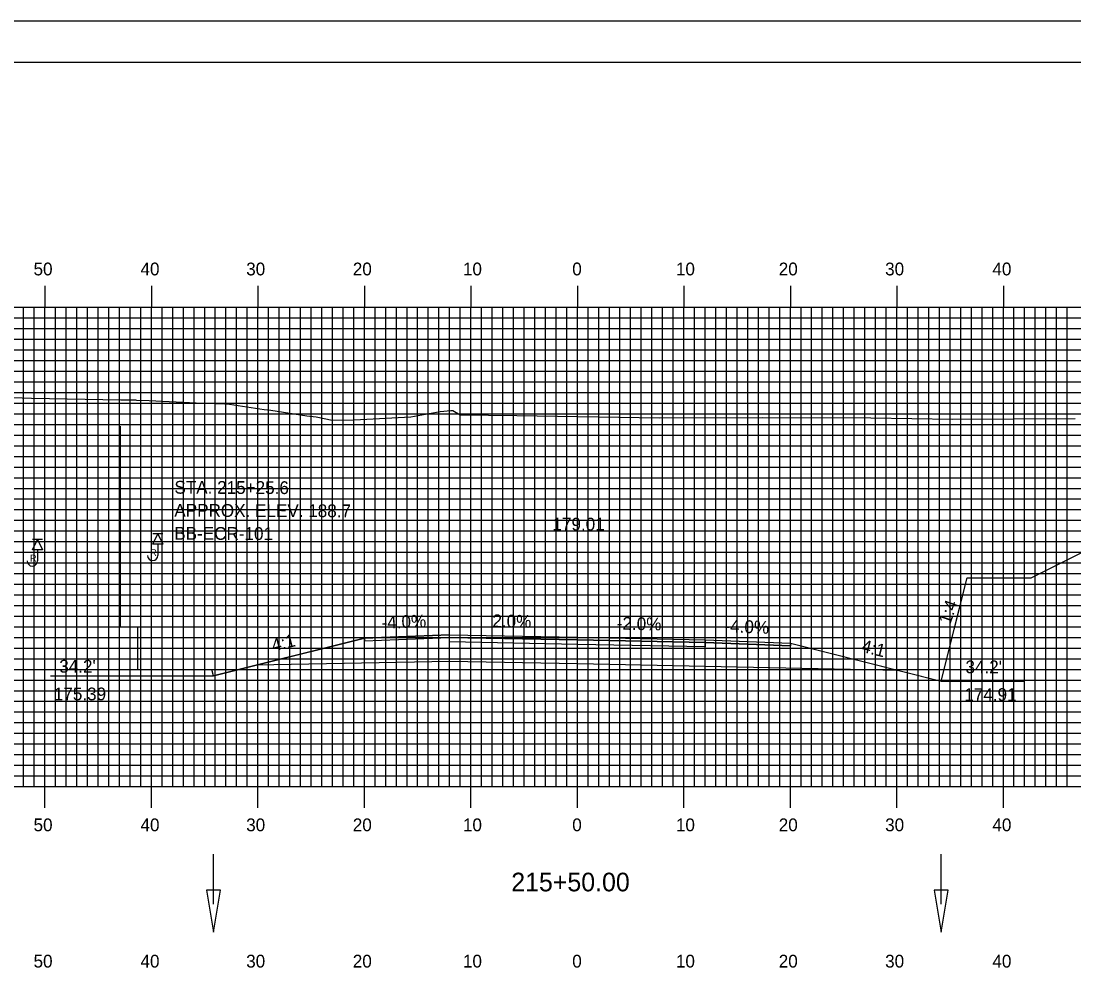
# Model space of a CAD drawing. Extents: x 1796027 to 1796370, y 442591 to 442811.
# Drawn here: x 1796140.1 to 1796239, y 442721.2 to 442810.5 of the extents above; entities that cross this region are included whole.
import ezdxf

# ---------------------------------------------------------------- set-up
doc = ezdxf.new("R2010")
doc.units = 0
for name, color, linetype in [('ANNOTATION', 7, 'Continuous'), ('BORDER', 7, 'Continuous'), ('BORING - REFUSAL', 7, 'Continuous'), ('D_Drainage_Ditch_Line', 7, 'Continuous'), ('D_Roadway_Centerline', 7, 'Continuous'), ('D_Roadway_Centerline_Text', 7, 'Continuous'), ('D_Roadway_Edge_Shoulder', 7, 'Continuous'), ('D_Roadway_Edge_TW', 7, 'Continuous'), ('D_Roadway_Pavement', 7, 'Continuous'), ('D_Roadway_SlopeLines', 7, 'Continuous'), ('D_Roadway_SubGrade', 7, 'Continuous'), ('H_V ANNOTATION', 7, 'Continuous'), ('MAJOR', 7, 'Continuous'), ('MINOR', 7, 'Continuous'), ('PDRAIN', 7, 'Continuous'), ('PLOT BOUNDARY', 7, 'Continuous'), ('S_Roadway_Centerline', 7, 'Continuous')]:
    doc.layers.add(name, color=color, linetype=linetype)

msp = doc.modelspace()

# ---------------------------------------------------------------- linework, layer by layer
at = {"layer": 'ANNOTATION'}
for p, q in [((1796227.566, 442752.571), (1796228.99, 442758.265)), ((1796149.492, 442753.665), (1796151.092, 442753.665)), ((1796151.092, 442753.665), (1796151.092, 442749.665)), ((1796226.566, 442748.571), (1796227.566, 442752.571)), ((1796158.218, 442749.051), (1796158.065, 442749.665))]:
    msp.add_line(p, q, dxfattribs=at)
for points in [[(1796149.492, 442753.665), (1796149.492, 442772.516)], [(1796151.092, 442749.665), (1796158.065, 442749.665)]]:
    msp.add_lwpolyline(points, dxfattribs=at)
at = {"layer": 'BORDER'}
msp.add_lwpolyline([(1796042.792, 442596.665), (1796362.792, 442596.665), (1796362.792, 442806.665), (1796042.792, 442806.665)], close=True, dxfattribs=at)
at = {"layer": 'BORING - REFUSAL'}
for p, q in [((1796142.172, 442761.865), (1796141.212, 442761.865)), ((1796153.472, 442762.381), (1796152.512, 442762.381)), ((1796141.692, 442760.906), (1796141.692, 442759.847)), ((1796152.992, 442761.421), (1796152.992, 442760.362))]:
    msp.add_line(p, q, dxfattribs=at)
for points in [[(1796141.692, 442761.865), (1796142.172, 442760.906), (1796141.212, 442760.906)], [(1796152.992, 442762.381), (1796153.472, 442761.421), (1796152.512, 442761.421)]]:
    msp.add_lwpolyline(points, close=True, dxfattribs=at)
for centre in [(1796152.507, 442760.362), (1796141.207, 442759.847)]:
    msp.add_arc(centre, 0.485, 180, 0, dxfattribs=at)
at = {"layer": 'D_Drainage_Ditch_Line'}
for p, q in [((1796158.219, 442727.626), (1796158.218, 442732.325)), ((1796226.567, 442727.626), (1796226.567, 442732.325))]:
    msp.add_line(p, q, dxfattribs=at)
for points in [[(1796158.875, 442728.939), (1796157.563, 442728.939), (1796158.219, 442725.002)], [(1796227.223, 442728.939), (1796225.911, 442728.939), (1796226.567, 442725.002)]]:
    msp.add_lwpolyline(points, close=True, dxfattribs=at)
at = {"layer": 'D_Roadway_Centerline'}
msp.add_lwpolyline([(1796158.218, 442749.051), (1796162.218, 442750.051), (1796172.392, 442752.595), (1796180.392, 442752.915), (1796192.392, 442752.675), (1796204.392, 442752.435), (1796212.392, 442752.115), (1796222.566, 442749.571), (1796226.566, 442748.571), (1796228.99, 442758.265)], dxfattribs=at)
at = {"layer": 'D_Roadway_Edge_Shoulder'}
for points in [[(1796180.392, 442752.915), (1796172.392, 442752.595), (1796172.392, 442752.345), (1796180.392, 442752.665)], [(1796204.392, 442752.435), (1796212.392, 442752.115), (1796212.392, 442751.865), (1796204.392, 442752.185)]]:
    msp.add_lwpolyline(points, close=True, dxfattribs=at)
at = {"layer": 'D_Roadway_Edge_TW'}
msp.add_lwpolyline([(1796180.392, 442752.665), (1796180.392, 442752.915), (1796192.392, 442752.675), (1796204.392, 442752.435), (1796204.392, 442752.185), (1796192.392, 442752.425)], close=True, dxfattribs=at)
at = {"layer": 'D_Roadway_Pavement'}
msp.add_lwpolyline([(1796180.392, 442752.248), (1796180.392, 442752.665), (1796192.392, 442752.425), (1796204.392, 442752.185), (1796204.392, 442751.768), (1796192.392, 442752.008)], close=True, dxfattribs=at)
at = {"layer": 'D_Roadway_SlopeLines'}
for points in [[(1796228.99, 442758.265), (1796234.99, 442758.265), (1796262.53, 442772.035)], [(1796172.392, 442752.595), (1796158.218, 442749.051)], [(1796212.392, 442752.115), (1796226.566, 442748.571)]]:
    msp.add_lwpolyline(points, dxfattribs=at)
at = {"layer": 'D_Roadway_SubGrade'}
msp.add_lwpolyline([(1796180.392, 442750.415), (1796162.218, 442750.051), (1796172.392, 442752.595), (1796172.392, 442752.345), (1796180.392, 442752.665), (1796192.392, 442752.425), (1796204.392, 442752.185), (1796212.392, 442751.865), (1796212.392, 442752.115), (1796222.566, 442749.571), (1796204.392, 442749.935), (1796192.392, 442750.175)], close=True, dxfattribs=at)
at = {"layer": 'MAJOR'}
for p, q in [((1796142.392, 442785.669), (1796142.392, 442783.665)), ((1796152.392, 442785.669), (1796152.392, 442783.665)), ((1796162.392, 442785.669), (1796162.392, 442783.665)), ((1796172.392, 442785.669), (1796172.392, 442783.665)), ((1796182.392, 442785.669), (1796182.392, 442783.665)), ((1796192.392, 442785.669), (1796192.392, 442783.665)), ((1796202.392, 442785.669), (1796202.392, 442783.665)), ((1796212.392, 442785.669), (1796212.392, 442783.665)), ((1796222.392, 442785.669), (1796222.392, 442783.665)), ((1796232.392, 442785.669), (1796232.392, 442783.665)), ((1796052.392, 442783.665), (1796332.392, 442783.665)), ((1796052.392, 442783.665), (1796332.392, 442783.665)), ((1796142.392, 442738.665), (1796142.392, 442783.665)), ((1796152.392, 442738.665), (1796152.392, 442783.665)), ((1796162.392, 442738.665), (1796162.392, 442783.665)), ((1796172.392, 442738.665), (1796172.392, 442783.665)), ((1796182.392, 442738.665), (1796182.392, 442783.665)), ((1796192.392, 442738.665), (1796192.392, 442783.665)), ((1796202.392, 442738.665), (1796202.392, 442783.665)), ((1796212.392, 442738.665), (1796212.392, 442783.665)), ((1796222.392, 442738.665), (1796222.392, 442783.665)), ((1796232.392, 442738.665), (1796232.392, 442783.665)), ((1796052.392, 442778.665), (1796332.392, 442778.665)), ((1796052.392, 442773.665), (1796332.392, 442773.665)), ((1796052.392, 442768.665), (1796332.392, 442768.665)), ((1796052.392, 442763.665), (1796332.392, 442763.665)), ((1796052.392, 442758.665), (1796332.392, 442758.665)), ((1796052.392, 442753.665), (1796332.392, 442753.665)), ((1796052.392, 442748.665), (1796332.392, 442748.665)), ((1796052.392, 442743.665), (1796332.392, 442743.665)), ((1796052.392, 442738.665), (1796332.392, 442738.665)), ((1796052.392, 442738.665), (1796332.392, 442738.665)), ((1796142.392, 442736.661), (1796142.392, 442738.665)), ((1796152.392, 442736.661), (1796152.392, 442738.665)), ((1796162.392, 442736.661), (1796162.392, 442738.665)), ((1796172.392, 442736.661), (1796172.392, 442738.665)), ((1796182.392, 442736.661), (1796182.392, 442738.665)), ((1796192.392, 442736.661), (1796192.392, 442738.665)), ((1796202.392, 442736.661), (1796202.392, 442738.665)), ((1796212.392, 442736.661), (1796212.392, 442738.665)), ((1796222.392, 442736.661), (1796222.392, 442738.665)), ((1796232.392, 442736.661), (1796232.392, 442738.665))]:
    msp.add_line(p, q, dxfattribs=at)
at = {"layer": 'MINOR'}
for p, q in [((1796140.392, 442738.665), (1796140.392, 442783.665)), ((1796141.392, 442738.665), (1796141.392, 442783.665)), ((1796143.392, 442738.665), (1796143.392, 442783.665)), ((1796144.392, 442738.665), (1796144.392, 442783.665)), ((1796145.392, 442738.665), (1796145.392, 442783.665)), ((1796146.392, 442738.665), (1796146.392, 442783.665)), ((1796147.392, 442738.665), (1796147.392, 442783.665)), ((1796148.392, 442738.665), (1796148.392, 442783.665)), ((1796149.392, 442738.665), (1796149.392, 442783.665)), ((1796150.392, 442738.665), (1796150.392, 442783.665)), ((1796151.392, 442738.665), (1796151.392, 442783.665)), ((1796153.392, 442738.665), (1796153.392, 442783.665)), ((1796154.392, 442738.665), (1796154.392, 442783.665)), ((1796155.392, 442738.665), (1796155.392, 442783.665)), ((1796156.392, 442738.665), (1796156.392, 442783.665)), ((1796157.392, 442738.665), (1796157.392, 442783.665)), ((1796158.392, 442738.665), (1796158.392, 442783.665)), ((1796159.392, 442738.665), (1796159.392, 442783.665)), ((1796160.392, 442738.665), (1796160.392, 442783.665)), ((1796161.392, 442738.665), (1796161.392, 442783.665)), ((1796163.392, 442738.665), (1796163.392, 442783.665)), ((1796164.392, 442738.665), (1796164.392, 442783.665)), ((1796165.392, 442738.665), (1796165.392, 442783.665)), ((1796166.392, 442738.665), (1796166.392, 442783.665)), ((1796167.392, 442738.665), (1796167.392, 442783.665)), ((1796168.392, 442738.665), (1796168.392, 442783.665)), ((1796169.392, 442738.665), (1796169.392, 442783.665)), ((1796170.392, 442738.665), (1796170.392, 442783.665)), ((1796171.392, 442738.665), (1796171.392, 442783.665)), ((1796173.392, 442738.665), (1796173.392, 442783.665)), ((1796174.392, 442738.665), (1796174.392, 442783.665)), ((1796175.392, 442738.665), (1796175.392, 442783.665)), ((1796176.392, 442738.665), (1796176.392, 442783.665)), ((1796177.392, 442738.665), (1796177.392, 442783.665)), ((1796178.392, 442738.665), (1796178.392, 442783.665)), ((1796179.392, 442738.665), (1796179.392, 442783.665)), ((1796180.392, 442738.665), (1796180.392, 442783.665)), ((1796181.392, 442738.665), (1796181.392, 442783.665)), ((1796183.392, 442738.665), (1796183.392, 442783.665)), ((1796184.392, 442738.665), (1796184.392, 442783.665)), ((1796185.392, 442738.665), (1796185.392, 442783.665)), ((1796186.392, 442738.665), (1796186.392, 442783.665)), ((1796187.392, 442738.665), (1796187.392, 442783.665)), ((1796188.392, 442738.665), (1796188.392, 442783.665)), ((1796189.392, 442738.665), (1796189.392, 442783.665)), ((1796190.392, 442738.665), (1796190.392, 442783.665)), ((1796191.392, 442738.665), (1796191.392, 442783.665)), ((1796193.392, 442738.665), (1796193.392, 442783.665)), ((1796194.392, 442738.665), (1796194.392, 442783.665)), ((1796195.392, 442738.665), (1796195.392, 442783.665)), ((1796196.392, 442738.665), (1796196.392, 442783.665)), ((1796197.392, 442738.665), (1796197.392, 442783.665)), ((1796198.392, 442738.665), (1796198.392, 442783.665)), ((1796199.392, 442738.665), (1796199.392, 442783.665)), ((1796200.392, 442738.665), (1796200.392, 442783.665)), ((1796201.392, 442738.665), (1796201.392, 442783.665)), ((1796203.392, 442738.665), (1796203.392, 442783.665)), ((1796204.392, 442738.665), (1796204.392, 442783.665)), ((1796205.392, 442738.665), (1796205.392, 442783.665)), ((1796206.392, 442738.665), (1796206.392, 442783.665)), ((1796207.392, 442738.665), (1796207.392, 442783.665)), ((1796208.392, 442738.665), (1796208.392, 442783.665)), ((1796209.392, 442738.665), (1796209.392, 442783.665)), ((1796210.392, 442738.665), (1796210.392, 442783.665)), ((1796211.392, 442738.665), (1796211.392, 442783.665)), ((1796213.392, 442738.665), (1796213.392, 442783.665)), ((1796214.392, 442738.665), (1796214.392, 442783.665)), ((1796215.392, 442738.665), (1796215.392, 442783.665)), ((1796216.392, 442738.665), (1796216.392, 442783.665)), ((1796217.392, 442738.665), (1796217.392, 442783.665)), ((1796218.392, 442738.665), (1796218.392, 442783.665)), ((1796219.392, 442738.665), (1796219.392, 442783.665)), ((1796220.392, 442738.665), (1796220.392, 442783.665)), ((1796221.392, 442738.665), (1796221.392, 442783.665)), ((1796223.392, 442738.665), (1796223.392, 442783.665)), ((1796224.392, 442738.665), (1796224.392, 442783.665)), ((1796225.392, 442738.665), (1796225.392, 442783.665)), ((1796226.392, 442738.665), (1796226.392, 442783.665)), ((1796227.392, 442738.665), (1796227.392, 442783.665)), ((1796228.392, 442738.665), (1796228.392, 442783.665)), ((1796229.392, 442738.665), (1796229.392, 442783.665)), ((1796230.392, 442738.665), (1796230.392, 442783.665)), ((1796231.392, 442738.665), (1796231.392, 442783.665)), ((1796233.392, 442738.665), (1796233.392, 442783.665)), ((1796234.392, 442738.665), (1796234.392, 442783.665)), ((1796235.392, 442738.665), (1796235.392, 442783.665)), ((1796236.392, 442738.665), (1796236.392, 442783.665)), ((1796237.392, 442738.665), (1796237.392, 442783.665)), ((1796238.392, 442738.665), (1796238.392, 442783.665)), ((1796052.392, 442782.665), (1796332.392, 442782.665)), ((1796052.392, 442781.665), (1796332.392, 442781.665)), ((1796052.392, 442780.665), (1796332.392, 442780.665)), ((1796052.392, 442779.665), (1796332.392, 442779.665)), ((1796052.392, 442777.665), (1796332.392, 442777.665)), ((1796052.392, 442776.665), (1796332.392, 442776.665)), ((1796052.392, 442775.665), (1796332.392, 442775.665)), ((1796052.392, 442774.665), (1796332.392, 442774.665)), ((1796052.392, 442772.665), (1796332.392, 442772.665)), ((1796052.392, 442771.665), (1796332.392, 442771.665)), ((1796052.392, 442770.665), (1796332.392, 442770.665)), ((1796052.392, 442769.665), (1796332.392, 442769.665)), ((1796052.392, 442767.665), (1796332.392, 442767.665)), ((1796052.392, 442766.665), (1796332.392, 442766.665)), ((1796052.392, 442765.665), (1796332.392, 442765.665)), ((1796052.392, 442764.665), (1796332.392, 442764.665)), ((1796052.392, 442762.665), (1796332.392, 442762.665)), ((1796052.392, 442761.665), (1796332.392, 442761.665)), ((1796052.392, 442760.665), (1796332.392, 442760.665)), ((1796052.392, 442759.665), (1796332.392, 442759.665)), ((1796052.392, 442757.665), (1796332.392, 442757.665)), ((1796052.392, 442756.665), (1796332.392, 442756.665)), ((1796052.392, 442755.665), (1796332.392, 442755.665)), ((1796052.392, 442754.665), (1796332.392, 442754.665)), ((1796052.392, 442752.665), (1796332.392, 442752.665)), ((1796052.392, 442751.665), (1796332.392, 442751.665)), ((1796052.392, 442750.665), (1796332.392, 442750.665)), ((1796052.392, 442749.665), (1796332.392, 442749.665)), ((1796052.392, 442747.665), (1796332.392, 442747.665)), ((1796052.392, 442746.665), (1796332.392, 442746.665)), ((1796052.392, 442745.665), (1796332.392, 442745.665)), ((1796052.392, 442744.665), (1796332.392, 442744.665)), ((1796052.392, 442742.665), (1796332.392, 442742.665)), ((1796052.392, 442741.665), (1796332.392, 442741.665)), ((1796052.392, 442740.665), (1796332.392, 442740.665)), ((1796052.392, 442739.665), (1796332.392, 442739.665))]:
    msp.add_line(p, q, dxfattribs=at)
at = {"layer": 'PDRAIN'}
for p, q in [((1796142.928, 442749.051), (1796158.218, 442749.051)), ((1796226.566, 442748.571), (1796234.298, 442748.571))]:
    msp.add_line(p, q, dxfattribs=at)
at = {"layer": 'PLOT BOUNDARY'}
msp.add_lwpolyline([(1796026.605, 442590.547), (1796366.605, 442590.547), (1796366.605, 442810.547), (1796026.605, 442810.547)], close=True, dxfattribs=at)
at = {"layer": 'S_Roadway_Centerline'}
msp.add_lwpolyline([(1796138.461, 442775.222), (1796141.119, 442775.146), (1796149.521, 442774.982), (1796150.902, 442774.969), (1796150.989, 442774.95), (1796152.163, 442774.927), (1796156.605, 442774.71), (1796159.275, 442774.595), (1796159.718, 442774.578), (1796162.99, 442774.085), (1796163.593, 442774.006), (1796166.979, 442773.463), (1796167.872, 442773.386), (1796169.369, 442773.059), (1796171.444, 442773.085), (1796176.749, 442773.382), (1796179.502, 442773.878), (1796180.495, 442773.97), (1796180.705, 442773.962), (1796181.375, 442773.564), (1796186.695, 442773.51), (1796200.093, 442773.287), (1796209.741, 442773.317), (1796219.933, 442773.299), (1796227.635, 442773.155), (1796239.136, 442773.233)], dxfattribs=at)

# ---------------------------------------------------------------- texts
at = {"layer": 'ANNOTATION'}
for s, rotation, p in [('1:4', 70.51601, (1796227.395, 442753.811)), ('1:4', 70.51601, (1796227.395, 442753.811)), ('-4.0%', 2.29061, (1796174.024, 442753.462)), ('2.0%', 358.85424, (1796184.399, 442753.635)), ('-2.0%', 358.85424, (1796196.078, 442753.402)), ('-4.0%', 357.70939, (1796206.184, 442753.165)), ('4:1', 14.03624, (1796163.841, 442751.319)), ('4:1', 345.96376, (1796218.985, 442751.328))]:
    msp.add_text(s, height=1.2, rotation=rotation, dxfattribs=at).set_placement(p)
for s, p in [("34.2'", (1796143.734, 442749.359)), ("34.2'", (1796228.837, 442749.298)), ('175.39', (1796143.225, 442746.759)), ('174.91', (1796228.725, 442746.698))]:
    msp.add_text(s, height=1.2, dxfattribs=at).set_placement(p)
at = {"layer": 'BORING - REFUSAL'}
for s, p in [('STA. 215+25.6', (1796154.547, 442766.164)), ('APPROX. ELEV. 188.7', (1796154.54, 442764.004)), ('BB-ECR-101', (1796154.533, 442761.844))]:
    msp.add_text(s, height=1.2, rotation=359.81416, dxfattribs=at).set_placement(p)
for p in [(1796152.283, 442760.307), (1796140.983, 442759.791)]:
    msp.add_text('R', height=0.64, dxfattribs=at).set_placement(p)
at = {"layer": 'D_Roadway_Centerline'}
for s, p in [('C', (1796192.387, 442752.675)), ('L', (1796192.392, 442752.668))]:
    msp.add_text(s, height=0.0146, dxfattribs=at).set_placement(p)
at = {"layer": 'D_Roadway_Centerline_Text'}
msp.add_text('179.01', height=1.2, dxfattribs=at).set_placement((1796190.049, 442762.705))
at = {"layer": 'H_V ANNOTATION'}
for s, height, p in [('50', 1.2, (1796141.321, 442786.665)), ('40', 1.2, (1796151.364, 442786.665)), ('30', 1.2, (1796161.29, 442786.665)), ('20', 1.2, (1796171.3, 442786.665)), ('10', 1.2, (1796181.643, 442786.665)), ('0', 1.2, (1796191.91, 442786.665)), ('10', 1.2, (1796201.643, 442786.665)), ('20', 1.2, (1796211.3, 442786.665)), ('30', 1.2, (1796221.29, 442786.665)), ('40', 1.2, (1796231.364, 442786.665)), ('50', 1.2, (1796141.321, 442734.465)), ('40', 1.2, (1796151.364, 442734.465)), ('30', 1.2, (1796161.29, 442734.465)), ('20', 1.2, (1796171.3, 442734.465)), ('10', 1.2, (1796181.643, 442734.465)), ('0', 1.2, (1796191.91, 442734.465)), ('10', 1.2, (1796201.643, 442734.465)), ('20', 1.2, (1796211.3, 442734.465)), ('30', 1.2, (1796221.29, 442734.465)), ('40', 1.2, (1796231.364, 442734.465)), ('215+50.00', 1.75, (1796186.181, 442728.821)), ('50', 1.2, (1796141.321, 442721.665)), ('40', 1.2, (1796151.364, 442721.665)), ('30', 1.2, (1796161.29, 442721.665)), ('20', 1.2, (1796171.3, 442721.665)), ('10', 1.2, (1796181.643, 442721.665)), ('0', 1.2, (1796191.91, 442721.665)), ('10', 1.2, (1796201.643, 442721.665)), ('20', 1.2, (1796211.3, 442721.665)), ('30', 1.2, (1796221.29, 442721.665)), ('40', 1.2, (1796231.364, 442721.665))]:
    msp.add_text(s, height=height, dxfattribs=at).set_placement(p)

doc.saveas('drawing.dxf')
